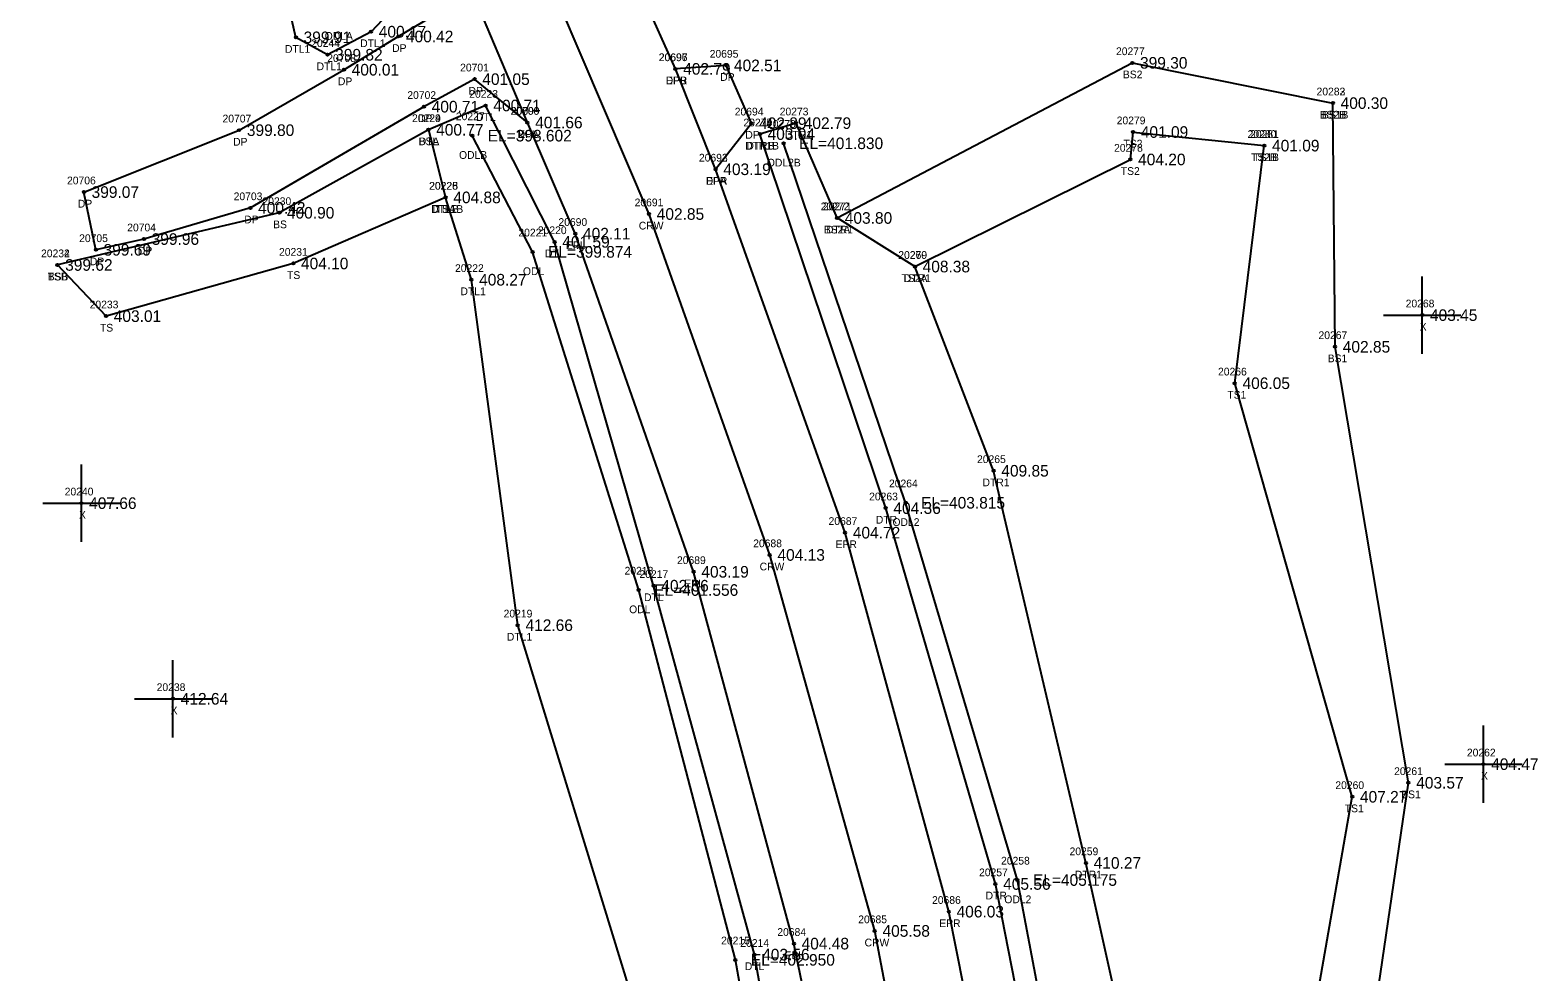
# Model space of a CAD drawing. Extents: x 2186623 to 2187804, y 1079975 to 1082766.
# Drawn here: x 2187544.4 to 2187739.5, y 1080883.4 to 1081005.2 of the extents above; entities that cross this region are included whole.
import ezdxf

# ---------------------------------------------------------------- set-up
doc = ezdxf.new("R2010")
doc.units = 0
for name, color, linetype in [('RD_DTM_BkLn1', 7, 'Continuous'), ('RD_DTM_BkLn2', 7, 'Continuous'), ('RD_DTM_BkLn_txCode', 7, 'Continuous'), ('RD_EX_Driveway', 7, 'Continuous'), ('RD_EX_Driveway_txCode', 7, 'Continuous'), ('RD_EX_H2O', 7, 'Continuous'), ('RD_EX_H2O_txCode', 7, 'Continuous'), ('RD_EX_Misc', 7, 'Continuous'), ('RD_EX_Misc_txCode', 7, 'Continuous'), ('RD_EX_Road', 7, 'Continuous'), ('RD_EX_Road_txCode', 7, 'Continuous'), ('RD_EX_TX_Driveway_ELEV', 7, 'Continuous'), ('RD_EX_TX_H2O_ELEV', 7, 'Continuous'), ('RD_EX_TX_Misc_ELEV', 7, 'Continuous'), ('RD_EX_TX_Road_ELEV', 7, 'Continuous'), ('RD_HC_Survey_ELEV', 7, 'Continuous'), ('RD_HC_Survey_txCode', 7, 'Continuous'), ('RD_SMD_Locator', 7, 'Continuous')]:
    doc.layers.add(name, color=color, linetype=linetype)

msp = doc.modelspace()

# ---------------------------------------------------------------- linework, layer by layer
at = {"layer": 'RD_DTM_BkLn1'}
msp.add_lwpolyline([(2187642.24, 1080529.1), (2187655.35, 1080580.74), (2187664.65, 1080633.05), (2187670.02, 1080686.16), (2187671.29, 1080737.22), (2187669.06, 1080788.31), (2187662.87, 1080840.34), (2187653.68, 1080888.67), (2187640.09, 1080937.32), (2187624.47, 1080981.43), (2187604.07, 1081029.14), (2187583.1, 1081073.79), (2187561.48, 1081119.01), (2187517.22, 1081209.7), (2187473.58, 1081297.58), (2187444.5, 1081356.52)], dxfattribs=at)
at = {"layer": 'RD_DTM_BkLn2'}
for points in [[(2187648.8, 1080980.92), (2187687, 1081000.99), (2187712.95, 1080995.78)], [(2187696.24, 1080770.61), (2187707.66, 1080784.65), (2187713.84, 1080847.23), (2187722.73, 1080907.84), (2187713.23, 1080964.25), (2187712.95, 1080995.78)], [(2187595.93, 1080992.33), (2187576.62, 1080981.59), (2187547.93, 1080974.84)], [(2187658.87, 1080974.63), (2187686.75, 1080988.49), (2187687.1, 1080992.04), (2187704.08, 1080990.28)], [(2187696.24, 1080770.61), (2187699.18, 1080787.87), (2187704.96, 1080846.08), (2187715.45, 1080906.03), (2187700.26, 1080959.54), (2187704.08, 1080990.28)], [(2187598.15, 1080983.58), (2187578.44, 1080975.03), (2187554.22, 1080968.22), (2187547.93, 1080974.84)]]:
    msp.add_lwpolyline(points, dxfattribs=at)
at = {"layer": 'RD_EX_Driveway'}
for points in [[(2187608.74, 1080993.27), (2187601.9, 1080998.88), (2187595.35, 1080995.32), (2187572.89, 1080982.22), (2187559.12, 1080978.19), (2187552.9, 1080976.8), (2187551.35, 1080984.27), (2187571.44, 1080992.28), (2187585, 1081000.1), (2187592.02, 1081004.4), (2187601.62, 1081010.12)], [(2187633.08, 1080987.22), (2187637.71, 1080993.18), (2187634.46, 1081000.66), (2187627.89, 1081000.21)]]:
    msp.add_lwpolyline(points, dxfattribs=at)
at = {"layer": 'RD_EX_H2O'}
for points in [[(2187593.52, 1081010.36), (2187588.51, 1081005.02), (2187582.87, 1081002.04), (2187578.78, 1081004.29), (2187575.41, 1081019.13), (2187558.65, 1081058.39), (2187538.46, 1081107.97), (2187489.32, 1081194.13), (2187475.91, 1081211.07), (2187471.61, 1081215.59), (2187468.02, 1081230.92), (2187440.55, 1081280.43), (2187412.92, 1081337.64), (2187413.25, 1081344), (2187412.89, 1081353.32)], [(2187628.75, 1080548.98), (2187633.55, 1080546.58), (2187640.67, 1080583.21), (2187648.07, 1080635.07), (2187654.41, 1080685.61), (2187657.17, 1080737.23), (2187653.71, 1080787.25), (2187646.55, 1080837.2), (2187638.11, 1080885.61), (2187625.06, 1080933.34), (2187612.25, 1080977.83), (2187603.33, 1080995.47), (2187595.93, 1080992.33), (2187598.15, 1080983.58)], [(2187562.23, 1080319.5), (2187568.42, 1080315.11), (2187580.31, 1080331.23), (2187604.15, 1080372.39), (2187628.61, 1080422.33), (2187648.05, 1080470.41), (2187665.68, 1080522.02), (2187680.31, 1080574.99), (2187687.87, 1080629.9), (2187695.01, 1080683.54), (2187694.9, 1080734.97), (2187697.43, 1080791.38), (2187692.76, 1080844.49), (2187681, 1080897.47), (2187669.05, 1080948.21), (2187658.87, 1080974.63), (2187648.8, 1080980.92), (2187643.49, 1080993.19), (2187638.81, 1080991.77)], [(2187562.23, 1080319.5), (2187571.46, 1080336.44), (2187596.15, 1080376.32), (2187619.89, 1080425.96), (2187640.05, 1080472.96), (2187659.06, 1080523.62), (2187672.26, 1080576.6), (2187680.26, 1080630.9), (2187685.37, 1080684.02), (2187685.51, 1080735.27), (2187684.52, 1080789.93), (2187679.49, 1080842.82), (2187669.29, 1080894.75), (2187655.09, 1080943.38), (2187638.81, 1080991.77)], [(2187565.94, 1080319.75), (2187574.24, 1080334.65), (2187599.82, 1080374.71), (2187622.79, 1080424.73), (2187643.27, 1080471.86), (2187661.54, 1080523.04), (2187675.4, 1080576.09), (2187684.22, 1080630.65), (2187689.37, 1080683.55), (2187688.63, 1080735.08), (2187687.3, 1080790.16), (2187682.02, 1080843.09), (2187672.14, 1080895.26), (2187657.66, 1080944.07), (2187641.89, 1080990.58)], [(2187631.73, 1080551.81), (2187638.31, 1080583.45), (2187646.01, 1080635.33), (2187651.79, 1080685.78), (2187653.6, 1080737.19), (2187650.71, 1080786.89), (2187644.16, 1080836.84), (2187635.64, 1080884.93), (2187623.14, 1080932.78), (2187609.4, 1080976.53), (2187601.6, 1080991.57)], [(2187628.75, 1080548.98), (2187633.64, 1080583.93), (2187643.76, 1080635.97), (2187644.31, 1080686.27), (2187644.6, 1080737.08), (2187638, 1080785.34), (2187629.13, 1080834.57), (2187621.96, 1080881.13), (2187607.49, 1080928.23), (2187601.49, 1080972.93), (2187598.15, 1080983.58)]]:
    msp.add_lwpolyline(points, dxfattribs=at)
at = {"layer": 'RD_EX_Misc'}
for p, q in [((2187724.51, 1080963.35), (2187724.51, 1080973.35)), ((2187719.51, 1080968.35), (2187729.51, 1080968.35)), ((2187551.03, 1080939.02), (2187551.03, 1080949.02)), ((2187546.03, 1080944.02), (2187556.03, 1080944.02)), ((2187562.88, 1080913.71), (2187562.88, 1080923.71)), ((2187557.88, 1080918.71), (2187567.88, 1080918.71)), ((2187732.43, 1080905.25), (2187732.43, 1080915.25)), ((2187727.43, 1080910.25), (2187737.43, 1080910.25))]:
    msp.add_line(p, q, dxfattribs=at)
at = {"layer": 'RD_EX_Road'}
for points in [[(2187651.48, 1080526.2), (2187665.01, 1080578.16), (2187674.62, 1080631.42), (2187679.88, 1080684.75), (2187681.19, 1080736.83), (2187679.13, 1080789.32), (2187672.95, 1080842.22), (2187663.26, 1080891.17), (2187649.84, 1080940.2), (2187633.08, 1080987.22), (2187627.89, 1081000.21), (2187623.73, 1081009.59), (2187612.91, 1081033.05), (2187591.82, 1081078.16), (2187569.84, 1081123.17), (2187525.89, 1081213.51), (2187482.28, 1081301.55), (2187455.91, 1081356.42), (2187456.01, 1081362.23)], [(2187634.28, 1080538.44), (2187635.96, 1080545.92), (2187645.85, 1080582.79), (2187654.89, 1080634.55), (2187660.21, 1080686.53), (2187661.4, 1080737.75), (2187659.23, 1080788.01), (2187653.21, 1080838.63), (2187643.21, 1080887.03), (2187630.24, 1080935.14), (2187614.93, 1080978.89), (2187608.74, 1080993.27), (2187601.62, 1081010.12), (2187595.44, 1081025.31), (2187574.96, 1081069.91), (2187552.71, 1081114.46), (2187508.28, 1081205.07), (2187464.88, 1081292.44), (2187436.83, 1081349.11), (2187432.45, 1081350.83)]]:
    msp.add_lwpolyline(points, dxfattribs=at)
at = {"layer": 'RD_SMD_Locator'}
for centre in [(2187578.78, 1081004.29), (2187588.51, 1081005.02), (2187592.02, 1081004.4), (2187582.87, 1081002.04), (2187585, 1081000.1), (2187627.89, 1081000.21), (2187627.89, 1081000.21), (2187634.46, 1081000.66), (2187687, 1081000.99), (2187601.9, 1080998.88), (2187595.35, 1080995.32), (2187603.33, 1080995.47), (2187712.95, 1080995.78), (2187712.95, 1080995.78), (2187571.44, 1080992.28), (2187595.93, 1080992.33), (2187595.93, 1080992.33), (2187608.74, 1080993.27), (2187608.74, 1080993.27), (2187637.71, 1080993.18), (2187643.49, 1080993.19), (2187687.1, 1080992.04), (2187601.6, 1080991.57), (2187638.81, 1080991.77), (2187638.81, 1080991.77), (2187641.89, 1080990.58), (2187704.08, 1080990.28), (2187704.08, 1080990.28), (2187686.75, 1080988.49), (2187633.08, 1080987.22), (2187633.08, 1080987.22), (2187551.35, 1080984.27), (2187598.15, 1080983.58), (2187598.15, 1080983.58), (2187598.15, 1080983.58), (2187572.89, 1080982.22), (2187576.62, 1080981.59), (2187624.47, 1080981.43), (2187648.8, 1080980.92), (2187648.8, 1080980.92), (2187614.93, 1080978.89), (2187552.9, 1080976.8), (2187559.12, 1080978.19), (2187609.4, 1080976.53), (2187612.25, 1080977.83), (2187547.93, 1080974.84), (2187547.93, 1080974.84), (2187578.44, 1080975.03), (2187658.87, 1080974.63), (2187658.87, 1080974.63), (2187601.49, 1080972.93), (2187554.22, 1080968.22), (2187724.51, 1080968.35), (2187713.23, 1080964.25), (2187700.26, 1080959.54), (2187669.05, 1080948.21), (2187551.03, 1080944.02), (2187655.09, 1080943.38), (2187657.66, 1080944.07), (2187649.84, 1080940.2), (2187640.09, 1080937.32), (2187630.24, 1080935.14), (2187623.14, 1080932.78), (2187625.06, 1080933.34), (2187607.49, 1080928.23), (2187562.88, 1080918.71), (2187732.43, 1080910.25), (2187722.73, 1080907.84), (2187715.45, 1080906.03), (2187681, 1080897.47), (2187669.29, 1080894.75), (2187672.14, 1080895.26), (2187663.26, 1080891.17), (2187653.68, 1080888.67), (2187643.21, 1080887.03), (2187635.64, 1080884.93), (2187638.11, 1080885.61)]:
    msp.add_circle(centre, 0.15, dxfattribs=at)

# ---------------------------------------------------------------- texts
at = {"layer": 'RD_DTM_BkLn_txCode'}
for s, p in [('20277', (2187684.89, 1081001.99)), ('BS2', (2187685.78, 1080998.99)), ('20282', (2187710.84, 1080996.78)), ('20283', (2187710.84, 1080996.78)), ('20229', (2187593.81, 1080993.33)), ('BS2B', (2187711.25, 1080993.78)), ('BS1B', (2187711.54, 1080993.78)), ('20279', (2187684.98, 1080993.04)), ('20280', (2187701.92, 1080991.28)), ('20281', (2187702.24, 1080991.28)), ('BSA', (2187594.66, 1080990.33)), ('20278', (2187684.64, 1080989.49)), ('TS2', (2187685.86, 1080990.04)), ('TS2B', (2187702.36, 1080988.28)), ('TS1B', (2187702.64, 1080988.28)), ('TS2', (2187685.51, 1080986.49)), ('20228', (2187596.04, 1080984.58)), ('20230', (2187574.46, 1080982.59)), ('TSA', (2187596.87, 1080981.58)), ('20272', (2187646.68, 1080981.92)), ('BS', (2187575.84, 1080979.59)), ('BS2A', (2187647.09, 1080978.92)), ('20232', (2187545.81, 1080975.84)), ('20234', (2187545.81, 1080975.84)), ('20231', (2187576.6, 1080976.03)), ('20270', (2187656.72, 1080975.63)), ('TSB', (2187546.66, 1080972.84)), ('BSB', (2187546.67, 1080972.84)), ('TS', (2187577.64, 1080973.03)), ('TS2A', (2187657.14, 1080972.63)), ('20233', (2187552.1, 1080969.22)), ('TS', (2187553.43, 1080966.22)), ('20267', (2187711.09, 1080965.25)), ('BS1', (2187712.28, 1080962.25)), ('20266', (2187698.09, 1080960.54)), ('TS1', (2187699.3, 1080957.54)), ('20261', (2187720.87, 1080908.84)), ('20260', (2187713.27, 1080907.03)), ('BS1', (2187721.79, 1080905.84)), ('TS1', (2187714.49, 1080904.03))]:
    msp.add_text(s, height=1, dxfattribs=at).set_placement(p)
at = {"layer": 'RD_EX_Driveway_txCode'}
for s, p in [('20708', (2187582.84, 1081001.1)), ('DP', (2187591.24, 1081002.4)), ('20696', (2187625.72, 1081001.21)), ('20695', (2187632.32, 1081001.66)), ('20701', (2187600.03, 1080999.88)), ('DP', (2187584.22, 1080998.1)), ('DPB', (2187626.63, 1080998.21)), ('DP', (2187633.68, 1080998.66)), ('20702', (2187593.2, 1080996.32)), ('DP', (2187601.12, 1080996.88)), ('20707', (2187569.29, 1080993.28)), ('DP', (2187594.58, 1080993.32)), ('20700', (2187606.55, 1080994.27)), ('20694', (2187635.56, 1080994.18)), ('DPA', (2187607.47, 1080991.27)), ('DP', (2187570.66, 1080990.28)), ('DP', (2187636.93, 1080991.18)), ('20693', (2187630.93, 1080988.22)), ('20706', (2187549.17, 1080985.27)), ('DPA', (2187631.81, 1080985.22)), ('DP', (2187550.57, 1080982.27)), ('20703', (2187570.73, 1080983.22)), ('DP', (2187572.11, 1080980.22)), ('20705', (2187550.74, 1080977.8)), ('20704', (2187556.96, 1080979.19)), ('DP', (2187558.34, 1080976.19)), ('DP', (2187552.12, 1080974.8))]:
    msp.add_text(s, height=1, dxfattribs=at).set_placement(p)
at = {"layer": 'RD_EX_H2O_txCode'}
for s, p in [('20244', (2187580.76, 1081003.04)), ('ODLA', (2187582.51, 1081003.97)), ('DTL1', (2187587.1, 1081003.02)), ('DTL1', (2187577.37, 1081002.29)), ('DTL1', (2187581.46, 1081000.04)), ('20223', (2187601.21, 1080996.47)), ('20224', (2187593.81, 1080993.33)), ('20227', (2187599.48, 1080993.57)), ('DTL', (2187602.09, 1080993.47)), ('20273', (2187641.38, 1080994.19)), ('20274', (2187636.69, 1080992.77)), ('20275', (2187636.69, 1080992.77)), ('20276', (2187639.74, 1080992.58)), ('DTL', (2187594.69, 1080990.33)), ('DTR1B', (2187636.9, 1080989.77)), ('DTRB', (2187637.07, 1080989.77)), ('DTR1', (2187642.06, 1080991.19)), ('ODLB', (2187599.89, 1080988.57)), ('ODL2B', (2187639.72, 1080987.58)), ('20226', (2187596.01, 1080984.58)), ('20225', (2187596.04, 1080984.58)), ('DTL1B', (2187596.27, 1080981.58)), ('DTLB', (2187596.44, 1080981.58)), ('20271', (2187646.97, 1080981.92)), ('20221', (2187607.57, 1080978.53)), ('20220', (2187610.09, 1080978.83)), ('DTR1', (2187647.37, 1080978.92)), ('DTL', (2187611.01, 1080975.83)), ('20269', (2187656.73, 1080975.63)), ('20222', (2187599.37, 1080973.93)), ('ODL', (2187608.16, 1080973.53)), ('DTR1', (2187657.44, 1080972.63)), ('DTL1', (2187600.08, 1080970.93)), ('20265', (2187666.91, 1080949.21)), ('20263', (2187652.95, 1080944.38)), ('20264', (2187655.52, 1080946.07)), ('DTR1', (2187667.62, 1080946.21)), ('DTR', (2187653.82, 1080941.38)), ('ODL2', (2187655.97, 1080941.07)), ('20218', (2187621.31, 1080934.78)), ('20217', (2187623.23, 1080934.34)), ('DTL', (2187623.82, 1080931.34)), ('20219', (2187605.66, 1080929.23)), ('ODL', (2187621.9, 1080929.78)), ('DTL1', (2187606.08, 1080926.23)), ('20259', (2187678.88, 1080898.47)), ('20257', (2187667.17, 1080895.75)), ('20258', (2187670.02, 1080897.26)), ('DTR1', (2187679.57, 1080895.47)), ('DTR', (2187668.02, 1080892.75)), ('ODL2', (2187670.44, 1080892.26)), ('20215', (2187633.8, 1080886.93)), ('20214', (2187636.28, 1080886.61)), ('DTL', (2187636.87, 1080883.61))]:
    msp.add_text(s, height=1, dxfattribs=at).set_placement(p)
at = {"layer": 'RD_EX_Misc_txCode'}
for s, p in [('20268', (2187722.37, 1080969.35)), ('X', (2187724.19, 1080966.35)), ('20240', (2187548.87, 1080945.02)), ('X', (2187550.72, 1080942.02)), ('20238', (2187560.77, 1080919.71)), ('X', (2187562.57, 1080916.71)), ('20262', (2187730.29, 1080911.25)), ('X', (2187732.12, 1080908.25))]:
    msp.add_text(s, height=1, dxfattribs=at).set_placement(p)
at = {"layer": 'RD_EX_Road_txCode'}
for s, p in [('20697', (2187625.75, 1081001.21)), ('EPR', (2187626.66, 1080998.21)), ('20699', (2187606.6, 1080994.27)), ('EPL', (2187607.54, 1080991.27)), ('20692', (2187630.93, 1080988.22)), ('EPR', (2187631.85, 1080985.22)), ('20690', (2187612.75, 1080979.89)), ('EPL', (2187613.72, 1080976.89)), ('20687', (2187647.7, 1080941.2)), ('EPR', (2187648.61, 1080938.2)), ('20689', (2187628.09, 1080936.14)), ('EPL', (2187629.03, 1080933.14)), ('20686', (2187661.09, 1080892.17)), ('20684', (2187641.07, 1080888.03)), ('EPR', (2187662.03, 1080889.17)), ('EPL', (2187642, 1080885.03))]:
    msp.add_text(s, height=1, dxfattribs=at).set_placement(p)
at = {"layer": 'RD_EX_TX_Driveway_ELEV'}
for s, p in [('400.42', (2187593.02, 1081003.65)), ('400.01', (2187586, 1080999.35)), ('402.79', (2187628.89, 1080999.46)), ('402.51', (2187635.46, 1080999.91)), ('401.05', (2187602.9, 1080998.13)), ('400.71', (2187596.35, 1080994.57)), ('399.80', (2187572.44, 1080991.53)), ('401.66', (2187609.74, 1080992.52)), ('402.89', (2187638.71, 1080992.43)), ('403.19', (2187634.08, 1080986.47)), ('399.07', (2187552.35, 1080983.52)), ('400.42', (2187573.89, 1080981.47)), ('399.96', (2187560.12, 1080977.44)), ('399.69', (2187553.9, 1080976.05))]:
    msp.add_text(s, height=1.5, dxfattribs=at).set_placement(p)
at = {"layer": 'RD_EX_TX_H2O_ELEV'}
for s, p in [('399.91', (2187579.78, 1081003.54)), ('400.17', (2187589.51, 1081004.27)), ('399.82', (2187583.87, 1081001.29)), ('400.71', (2187604.33, 1080994.72)), ('400.77', (2187596.93, 1080991.58)), ('EL=398.602', (2187603.6, 1080990.82)), ('403.04', (2187639.81, 1080991.02)), ('403.04', (2187639.81, 1080991.02)), ('402.79', (2187644.49, 1080992.44)), ('EL=401.830', (2187643.89, 1080989.83)), ('404.88', (2187599.15, 1080982.83)), ('404.88', (2187599.15, 1080982.83)), ('403.80', (2187649.8, 1080980.17)), ('401.59', (2187613.25, 1080977.08)), ('EL=399.874', (2187611.4, 1080975.78)), ('408.38', (2187659.87, 1080973.88)), ('408.27', (2187602.49, 1080972.18)), ('409.85', (2187670.05, 1080947.46)), ('404.36', (2187656.09, 1080942.63)), ('EL=403.815', (2187659.66, 1080943.32)), ('402.36', (2187626.06, 1080932.59)), ('EL=401.556', (2187625.14, 1080932.03)), ('412.66', (2187608.49, 1080927.48)), ('410.27', (2187682, 1080896.72)), ('405.56', (2187670.29, 1080894)), ('EL=405.175', (2187674.14, 1080894.51)), ('EL=402.950', (2187637.64, 1080884.18)), ('403.56', (2187639.11, 1080884.86))]:
    msp.add_text(s, height=1.5, dxfattribs=at).set_placement(p)
at = {"layer": 'RD_EX_TX_Misc_ELEV'}
for s, p in [('399.30', (2187688, 1081000.24)), ('400.30', (2187713.95, 1080995.03)), ('400.30', (2187713.95, 1080995.03)), ('400.77', (2187596.93, 1080991.58)), ('401.09', (2187688.1, 1080991.29)), ('401.09', (2187705.08, 1080989.53)), ('401.09', (2187705.08, 1080989.53)), ('404.20', (2187687.75, 1080987.74)), ('404.88', (2187599.15, 1080982.83)), ('400.90', (2187577.62, 1080980.84)), ('403.80', (2187649.8, 1080980.17)), ('399.62', (2187548.93, 1080974.09)), ('399.62', (2187548.93, 1080974.09)), ('404.10', (2187579.44, 1080974.28)), ('408.38', (2187659.87, 1080973.88)), ('403.01', (2187555.22, 1080967.47)), ('403.45', (2187725.51, 1080967.6)), ('402.85', (2187714.23, 1080963.5)), ('406.05', (2187701.26, 1080958.79)), ('407.66', (2187552.03, 1080943.27)), ('412.64', (2187563.88, 1080917.96)), ('404.47', (2187733.43, 1080909.5)), ('403.57', (2187723.73, 1080907.09)), ('407.27', (2187716.45, 1080905.28))]:
    msp.add_text(s, height=1.5, dxfattribs=at).set_placement(p)
at = {"layer": 'RD_EX_TX_Road_ELEV'}
for s, p in [('402.79', (2187628.89, 1080999.46)), ('401.66', (2187609.74, 1080992.52)), ('403.19', (2187634.08, 1080986.47)), ('402.11', (2187615.93, 1080978.14)), ('404.72', (2187650.84, 1080939.45)), ('403.19', (2187631.24, 1080934.39)), ('406.03', (2187664.26, 1080890.42)), ('404.48', (2187644.21, 1080886.28))]:
    msp.add_text(s, height=1.5, dxfattribs=at).set_placement(p)
at = {"layer": 'RD_HC_Survey_ELEV'}
for s, p in [('402.85', (2187625.47, 1080980.68)), ('404.13', (2187641.09, 1080936.57)), ('405.58', (2187654.68, 1080887.92))]:
    msp.add_text(s, height=1.5, dxfattribs=at).set_placement(p)
at = {"layer": 'RD_HC_Survey_txCode'}
for s, p in [('20691', (2187622.61, 1080982.43)), ('CRW', (2187623.15, 1080979.43)), ('20688', (2187637.95, 1080938.32)), ('CRW', (2187638.78, 1080935.32)), ('20685', (2187651.54, 1080889.67)), ('CRW', (2187652.36, 1080886.67))]:
    msp.add_text(s, height=1, dxfattribs=at).set_placement(p)

doc.saveas('drawing.dxf')
